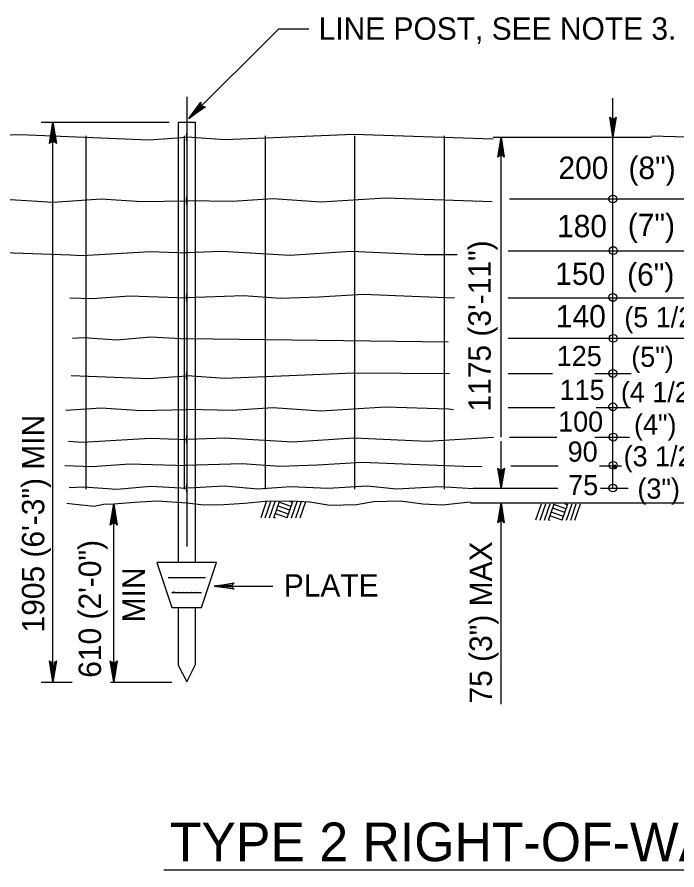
# Model space of a CAD drawing. Extents: x 13 to 918, y -903 to 879.
# Drawn here: x 225.6 to 317.7, y 510.7 to 629.8 of the extents above; entities that cross this region are included whole.
import ezdxf

# ---------------------------------------------------------------- set-up
doc = ezdxf.new("R2010")
doc.units = 0
for name, color, linetype in [('1', 7, 'Continuous'), ('2', 7, 'Continuous'), ('3', 7, 'Continuous')]:
    doc.layers.add(name, color=color, linetype=linetype)

msp = doc.modelspace()

# ---------------------------------------------------------------- linework, layer by layer
at = {"layer": '1'}
for p, q in [((223.78975, 596.94225), (232.98125, 596.60275)), ((260.3625, 562.12575), (259.58975, 559.8985)), ((260.9585, 562.12575), (260.171, 559.857)), ((261.55425, 562.12575), (260.76675, 559.857)), ((262.15, 562.12575), (261.3625, 559.857)), ((263.82725, 561.484), (262.13125, 562.0715)), ((264.03125, 562.12575), (263.246, 559.857)), ((264.0105, 562.01525), (263.696, 562.12575)), ((264.62725, 562.12575), (263.84175, 559.857)), ((265.221, 562.12575), (264.4375, 559.857)), ((265.81875, 562.12575), (265.0335, 559.857)), ((263.4605, 560.4215), (261.7625, 561.007)), ((263.64375, 560.95275), (261.948, 561.54225)), ((298.72725, 561.80075), (297.95425, 559.5735)), ((299.323, 561.80075), (298.5355, 559.532)), ((299.91875, 561.80075), (299.13125, 559.532)), ((300.51475, 561.80075), (299.72725, 559.532)), ((302.0085, 560.62775), (300.3125, 561.21725)), ((302.19175, 561.159), (300.496, 561.7465)), ((302.396, 561.80075), (301.6105, 559.532)), ((302.375, 561.69025), (302.0605, 561.80075)), ((302.99175, 561.80075), (302.20625, 559.532)), ((303.5855, 561.80075), (302.80225, 559.532)), ((304.1835, 561.80075), (303.398, 559.532)), ((261.64175, 559.857), (261.39375, 559.9445)), ((263.275, 559.89025), (261.57725, 560.47575)), ((300.00625, 559.532), (299.7585, 559.6195)), ((301.63975, 559.56525), (299.94175, 560.15075)), ((301.825, 560.0965), (300.12725, 560.682))]:
    msp.add_line(p, q, dxfattribs=at)
for centre in [(308.73756, 604.39154), (308.78556, 597.18779), (308.73756, 590.65654), (308.78556, 584.94154), (308.73756, 580.04304), (308.73756, 575.38454), (308.78556, 571.15829), (308.78556, 567.22029), (308.73756, 564.05079)]:
    msp.add_circle(centre, 0.54872, dxfattribs=at)
at = {"layer": '2'}
for p, q in [((249.25425, 618.65275), (249.25425, 555.87575)), ((308.7375, 613.009), (308.7375, 618.4445)), ((228.9375, 615.10275), (246.8335, 615.10275)), ((230.58975, 536.96725), (230.58975, 615.10275)), ((248.07925, 615.10275), (250.42925, 615.10275)), ((248.07925, 615.10275), (248.07925, 553.607)), ((250.42925, 615.10275), (250.42925, 553.6485)), ((235.19175, 613.19225), (235.19175, 563.89225)), ((248.9, 613.19225), (248.9, 563.89225)), ((260.19175, 613.19225), (260.19175, 563.89225)), ((272.69175, 613.19225), (272.69175, 563.89225)), ((285.19175, 613.19225), (285.19175, 608.861)), ((249.25425, 613.009), (249.25425, 613.009)), ((292.046, 613.009), (308.7375, 613.009)), ((293.14375, 575.27575), (293.14375, 613.009)), ((304.57725, 613.009), (314.125, 613.009)), ((308.7375, 564.05075), (308.7375, 613.009)), ((285.19175, 608.861), (285.19175, 563.89225)), ((249.25425, 604.15475), (249.25425, 604.15475)), ((294.2985, 604.3985), (306.06875, 604.3985)), ((306.06875, 604.3985), (326.86475, 604.3985)), ((249.25425, 596.86325), (249.25425, 596.86325)), ((294.11325, 597.16525), (322.37975, 597.16525)), ((249.25425, 590.61325), (249.25425, 590.61325)), ((294.11325, 590.59225), (321.51525, 590.59225)), ((249.25425, 584.884), (249.25425, 584.884)), ((294.11325, 584.9445), (318.634, 584.9445)), ((294.11325, 580.01725), (300.29375, 580.01725)), ((306.23975, 580.01725), (311.30425, 580.01725)), ((249.25425, 579.67575), (249.25425, 579.67575)), ((249.25425, 574.98825), (249.25425, 574.98825)), ((293.14375, 571.1485), (293.14375, 575.27575)), ((294.11325, 575.27575), (300.63975, 575.27575)), ((306.4125, 575.27575), (311.2085, 575.27575)), ((249.25425, 570.8215), (249.25425, 570.8215)), ((293.14375, 564.05075), (293.14375, 570.6045)), ((294.2985, 571.1485), (300.9085, 571.1485)), ((306.23975, 571.1485), (311.0355, 571.1485)), ((249.25425, 567.17575), (249.25425, 567.17575)), ((294.48375, 567.16325), (301.1, 567.16325)), ((306.85425, 567.16325), (309.9415, 567.16325)), ((249.25425, 564.05075), (249.25425, 564.05075)), ((289.21875, 564.05075), (301.05675, 564.05075)), ((307.012, 564.05075), (310.85375, 564.05075)), ((249.25425, 561.96725), (249.25425, 561.96725)), ((249.25425, 561.96725), (249.25425, 561.96725)), ((249.25425, 561.96725), (249.25425, 561.96725)), ((288.86675, 561.96725), (318.73125, 561.96725)), ((293.14375, 533.8715), (293.14375, 561.96725)), ((239.06875, 536.96725), (239.06875, 561.859)), ((253.421, 553.6445), (245.0875, 553.6445)), ((245.0875, 553.6445), (247.171, 547.3945)), ((251.3375, 547.3945), (253.421, 553.6445)), ((246.673, 551.561), (251.86875, 551.561)), ((253.10625, 550.357), (261.2605, 550.357)), ((247.171, 549.47775), (251.3375, 549.47775)), ((247.171, 547.3945), (251.3375, 547.3945)), ((248.07925, 547.409), (248.07925, 539.32775)), ((250.42925, 547.38825), (250.42925, 539.32775)), ((248.07925, 539.32775), (249.25425, 536.97775)), ((249.25425, 536.97775), (250.42925, 539.32775)), ((228.9375, 536.96725), (233.26475, 536.96725)), ((238.6105, 536.96725), (247.2, 536.96725))]:
    msp.add_line(p, q, dxfattribs=at)
for points in [[(97.69175, 613.009), (99.25425, 613.009), (104.871, 613.0965), (110.2605, 613.19225), (115.65225, 612.732), (126.71875, 613.19225), (142.046, 612.82775), (159.15625, 613.19225), (169.648, 612.732), (187.948, 613.28825), (206.725, 612.732), (226.04175, 613.384), (243.97725, 612.636), (249.25425, 613.009)], [(249.25425, 612.461), (249.2375, 612.65275), (249.26875, 612.76325), (249.24175, 612.911), (249.275, 613.05275), (249.2375, 613.211), (249.26475, 613.3695), (249.25425, 613.557)], [(292.0365, 612.72625), (272.5375, 613.384), (254.60225, 612.636), (249.325, 613.009)], [(400.8875, 613.009), (399.325, 613.009), (393.7085, 613.0965), (388.31875, 613.19225), (382.92725, 612.732), (371.8605, 613.19225), (356.5335, 612.82775), (339.423, 613.19225), (328.93125, 612.732), (314.13025, 613.18225)], [(97.69175, 604.15475), (99.25425, 604.15475), (105.121, 604.15475), (111.14375, 604.32575), (116.62925, 603.86525), (123.6125, 604.25075), (129.65425, 603.961), (135.67725, 604.25075), (142.46675, 603.86525), (151.4835, 604.4215), (157.621, 603.961), (165.04375, 604.32575), (171.27725, 604.057), (179.45, 604.057), (185.223, 604.25075), (191.821, 604.51725), (199.37925, 603.94225), (205.22925, 604.03825), (212.76875, 604.211), (221.59175, 604.4985), (230.60625, 603.94225), (237.30225, 604.40275), (242.9605, 604.03825), (249.25425, 604.15475)], [(249.25425, 603.607), (249.2375, 603.7985), (249.26875, 603.909), (249.24175, 604.057), (249.275, 604.1985), (249.2375, 604.357), (249.26475, 604.51525), (249.25425, 604.70275)], [(291.8775, 604.01225), (276.9875, 604.4985), (267.973, 603.94225), (261.27725, 604.40275), (255.61875, 604.03825), (249.325, 604.15475)], [(232.98125, 596.60275), (234.673, 596.49225), (244.15, 597.0485), (249.25425, 596.86325)], [(286.98575, 596.59175), (282.398, 596.58825), (272.175, 597.0485), (263.63975, 596.49225), (254.1625, 597.0485), (249.0585, 596.86325)], [(232.971, 590.607), (236.073, 590.4945), (241.29175, 590.859), (249.25425, 590.61325)], [(286.61875, 590.5465), (280.69175, 590.76325), (273.90225, 591.05075), (267.6875, 590.686), (262.39375, 590.4945), (257.175, 590.859), (249.2125, 590.61325)], [(249.25425, 590.06525), (249.2375, 590.257), (249.26875, 590.36725), (249.24175, 590.51525), (249.275, 590.657), (249.2375, 590.81525), (249.26475, 590.9735), (249.25425, 591.161)], [(233.3335, 584.986), (234.923, 585.0695), (239.52725, 584.7445), (244.26475, 585.1465), (249.25425, 584.884)], [(285.737, 584.3935), (249.25425, 584.884)], [(233.15425, 579.76525), (243.97725, 579.31325), (249.25425, 579.686)], [(249.25425, 579.12775), (249.2375, 579.3195), (249.26875, 579.42975), (249.24175, 579.57775), (249.275, 579.7195), (249.2375, 579.87775), (249.26475, 580.036), (249.25425, 580.2235)], [(285.929, 579.97525), (272.5375, 580.061), (254.60225, 579.31325), (249.325, 579.686)], [(232.4125, 574.911), (237.30225, 575.2465), (242.9605, 574.882), (249.25425, 574.9985)], [(286.5055, 574.98075), (285.8105, 575.05475), (276.9875, 575.34225), (267.973, 574.786), (261.27725, 575.2465), (255.61875, 574.882), (249.325, 574.9985)], [(232.77725, 570.5735), (234.673, 570.45075), (244.15, 571.007), (249.25425, 570.8215)], [(249.25425, 570.2735), (249.2375, 570.46525), (249.26875, 570.57575), (249.24175, 570.7235), (249.275, 570.86525), (249.2375, 571.0235), (249.26475, 571.182), (249.25425, 571.3695)], [(292.05725, 571.08525), (282.81875, 570.5465), (272.596, 571.007), (264.0605, 570.45075), (254.5835, 571.007), (249.47925, 570.8215)], [(232.25, 567.1945), (236.073, 567.057), (241.29175, 567.4215), (249.25425, 567.17575)], [(290.45225, 567.01725), (287.8855, 567.057), (280.5375, 567.32575), (273.748, 567.61325), (267.5335, 567.2485), (262.23975, 567.057), (257.021, 567.4215), (249.0585, 567.17575)], [(232.86925, 564.12875), (234.923, 564.236), (239.52725, 563.911), (244.26475, 564.31325), (249.25425, 564.05075)], [(249.25425, 563.50275), (249.2375, 563.6945), (249.26875, 563.80475), (249.24175, 563.95275), (249.275, 564.0945), (249.2375, 564.25275), (249.26475, 564.411), (249.25425, 564.5985)], [(289.21875, 563.94225), (284.64175, 564.236), (278.523, 563.89225), (274.4375, 564.31325), (268.95225, 563.96725), (263.8105, 564.236), (259.20625, 563.911), (254.46875, 564.31325), (249.47925, 564.05075)], [(232.512, 561.92725), (233.25425, 561.8195), (236.323, 561.532), (237.66675, 561.782), (239.06875, 561.859), (241.98125, 562.0695), (245.146, 562.261), (249.25425, 561.96725), (251.66875, 561.7235), (254.43125, 561.76325), (257.346, 561.91525), (260.2625, 562.20275), (263.946, 562.261), (266.4585, 562.107), (269.23975, 561.66725), (272.9605, 561.76325), (275.33975, 562.1465), (279.07925, 562.261), (282.225, 561.859), (285.025, 561.70475), (287.5375, 561.99225), (288.86675, 562.107)], [(246.673, 551.561), (246.973, 551.60075), (247.41475, 551.5215), (247.7355, 551.582), (248.096, 551.5215), (248.41675, 551.582), (248.77925, 551.50075), (249.1, 551.582), (249.44175, 551.5215), (249.74175, 551.561), (250.14375, 551.5215), (250.50425, 551.582), (250.90625, 551.54025), (251.22725, 551.60075), (251.548, 551.54025), (251.86875, 551.561)], [(247.171, 549.47775), (247.45425, 549.55475), (247.81475, 549.45475), (248.096, 549.51525), (248.398, 549.434), (248.698, 549.4945), (249.0605, 549.434), (249.321, 549.51525), (249.6605, 549.434), (249.9835, 549.51525), (250.34375, 549.434), (250.6855, 549.4945), (250.96475, 549.45475), (251.3375, 549.47775)]]:
    msp.add_lwpolyline(points, dxfattribs=at)
at = {"layer": '3'}
for p, q in [((249.57725, 615.60475), (262.11475, 628.14225)), ((262.11475, 628.14225), (266.28125, 628.14225)), ((308.7375, 604.40475), (308.7375, 604.40475)), ((308.7375, 597.1715), (308.7375, 597.1715)), ((308.7375, 590.5985), (308.7375, 590.5985)), ((308.7375, 584.95075), (308.7375, 584.95075)), ((308.7375, 580.0235), (308.7375, 580.0235)), ((308.7375, 575.282), (308.7375, 575.282)), ((308.7375, 571.15475), (308.7375, 571.15475)), ((308.7375, 567.1695), (308.7375, 567.1695)), ((308.7375, 564.111), (308.7375, 564.111)), ((246.05008, 510.74275), (380.81958, 510.74275))]:
    msp.add_line(p, q, dxfattribs=at)
for points in [[(251.6855, 617.24225), (251.47925, 617.309), (249.57725, 615.60475), (251.6855, 617.24225), (251.8625, 617.257), (249.57725, 615.60475), (251.28975, 617.4965), (251.221, 617.6965), (249.57725, 615.60475), (251.2335, 617.886), (251.221, 617.6965)], [(309.071, 615.657), (308.87925, 615.559), (308.7375, 613.009), (309.071, 615.657), (309.1855, 615.7945), (308.7375, 613.009), (308.6125, 615.557), (308.421, 615.65075), (308.7375, 613.009), (308.296, 615.7945), (308.421, 615.65075)], [(230.2335, 612.26525), (230.43975, 612.3715), (230.58975, 615.10275), (230.2335, 612.26525), (230.1085, 612.1195), (230.58975, 615.10275), (230.725, 612.3735), (230.92725, 612.2735), (230.58975, 615.10275), (231.06475, 612.1195), (230.92725, 612.2735)], [(292.8105, 610.361), (293.00225, 610.459), (293.14375, 613.009), (292.8105, 610.361), (292.696, 610.2235), (293.14375, 613.009), (293.26875, 610.461), (293.4605, 610.36725), (293.14375, 613.009), (293.5855, 610.2235), (293.4605, 610.36725)], [(293.47725, 566.6985), (293.2855, 566.60075), (293.14375, 564.05075), (293.47725, 566.6985), (293.59175, 566.836), (293.14375, 564.05075), (293.01875, 566.5985), (292.82725, 566.69225), (293.14375, 564.05075), (292.70225, 566.836), (292.82725, 566.69225)], [(292.8105, 559.3195), (293.00225, 559.41725), (293.14375, 561.96725), (292.8105, 559.3195), (292.696, 559.182), (293.14375, 561.96725), (293.26875, 559.4195), (293.4605, 559.32575), (293.14375, 561.96725), (293.5855, 559.182), (293.4605, 559.32575)], [(238.7125, 559.0215), (238.91875, 559.12775), (239.06875, 561.859), (238.7125, 559.0215), (238.5875, 558.87575), (239.06875, 561.859), (239.20425, 559.12975), (239.40625, 559.02975), (239.06875, 561.859), (239.54375, 558.87575), (239.40625, 559.02975)], [(255.75425, 550.0235), (255.65625, 550.21525), (253.10625, 550.357), (255.75425, 550.0235), (255.89175, 549.909), (253.10625, 550.357), (255.65425, 550.482), (255.748, 550.6735), (253.10625, 550.357), (255.89175, 550.7985), (255.748, 550.6735)], [(230.946, 539.80475), (230.73975, 539.6985), (230.58975, 536.96725), (230.946, 539.80475), (231.071, 539.95075), (230.58975, 536.96725), (230.45425, 539.6965), (230.25225, 539.7965), (230.58975, 536.96725), (230.11475, 539.95075), (230.25225, 539.7965)], [(239.425, 539.80475), (239.21875, 539.6985), (239.06875, 536.96725), (239.425, 539.80475), (239.55, 539.95075), (239.06875, 536.96725), (238.9335, 539.6965), (238.73125, 539.7965), (239.06875, 536.96725), (238.59375, 539.95075), (238.73125, 539.7965)]]:
    msp.add_lwpolyline(points, dxfattribs=at)

# ---------------------------------------------------------------- texts
at = {"layer": '1'}
for s, height, p in [('(8")', 3.124999, (310.91525, 607.17975)), ('(7")', 3.124999, (310.81925, 599.20775)), ('(6")', 3.124999, (310.723, 592.29225)), ('(5 1/2")', 2.812499, (310.3355, 586.4885)), ('(5")', 2.812499, (311.2995, 580.96575)), ('(4 1/2")', 2.812499, (309.85525, 576.02875)), ('(4")', 2.812499, (311.6835, 571.51425)), ('(3 1/2")', 2.812499, (310.2395, 567.077)), ('(3")', 2.812499, (312.16375, 562.5625))]:
    msp.add_text(s, height=height, dxfattribs=at).set_placement(p)
at = {"layer": '3'}
for s, height, p in [('LINE POST, SEE NOTE 3.', 3.1249995, (267.671, 626.61325)), ('200', 3.124999, (301.13625, 607.1835)), ('180', 3.124999, (300.944, 599.0515)), ('150', 3.124999, (300.6955, 592.398)), ('140', 3.124999, (300.77575, 586.46725)), ('125', 2.812499, (300.9055, 581.0785)), ('115', 2.812499, (301.298, 576.349)), ('100', 2.812499, (301.0975, 571.91925)), ('90', 2.812499, (302.42925, 567.7305)), ('.', 3.125, (308.4, 566.80475)), ('75', 2.812499, (302.49775, 563.0565)), ('PLATE', 3.124999, (262.8105, 548.89025)), ('TYPE 2 RIGHT-OF-WAY FENCE', 5.4020865, (246.89425, 511.95525))]:
    msp.add_text(s, height=height, dxfattribs=at).set_placement(p)
for s, height, p in [('1175 (3\'-11")', 3.1249995, (291.698, 574.72725)), ('1905 (6\'-3") MIN', 3.1249995, (229.38125, 543.8895)), ('610 (2\'-0")', 3.1249995, (237.301, 537.56475)), ('75 (3") MAX', 3.1249995, (291.853, 533.97175)), ('MIN', 3.124999, (243.421, 545.30275))]:
    msp.add_text(s, height=height, rotation=90, dxfattribs=at).set_placement(p)

doc.saveas('drawing.dxf')
